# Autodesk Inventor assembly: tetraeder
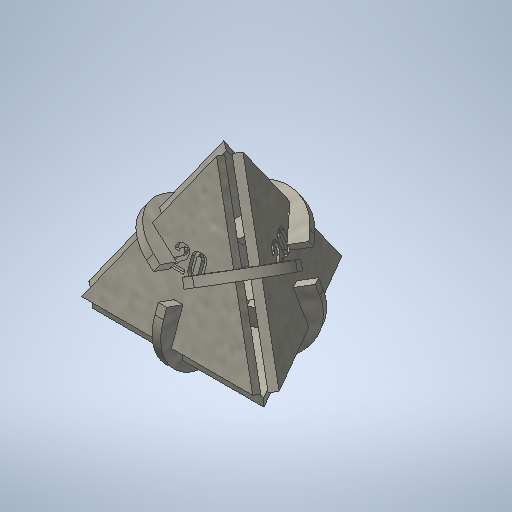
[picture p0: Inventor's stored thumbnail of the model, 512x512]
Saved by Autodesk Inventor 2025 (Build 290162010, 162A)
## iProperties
Created: 2025-02
Part Number: tetraeder
Material: Generisch
Document SubType Name: Assembly
Designer: BennF
Author: BennF
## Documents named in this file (3)
- C:\Users\BennF\OneDrive - Technische Universität Ilmenau\FabAcademy\week03\tetrahedron.iam
- C:\Users\BennF\OneDrive - Technische Universität Ilmenau\FabAcademy\week03\conector_71.ipt
- C:\Users\BennF\OneDrive - Technische Universität Ilmenau\FabAcademy\week03\triangular_tile.ipt
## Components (10 placed, 2 different names)
1. triangular_tile:1 — Mate:1, Mate:2, Mate:3, Mate:4, Mate:5, Mate:6, Mate:7, Mate:8, Mate:9
2. triangular_tile:2 — Mate:10, Mate:11, Mate:12, Mate:19, Mate:20, Mate:21
3. triangular_tile:3 — Mate:13, Mate:14, Mate:15, Mate:22, Mate:23, Mate:24
4. triangular_tile:4 — Mate:16, Mate:17, Mate:18, Mate:25, Mate:26, Mate:27
5. conector_71:1 — Mate:1, Mate:2, Mate:3, Mate:10, Mate:11, Mate:12
6. conector_71:2 — Mate:4, Mate:5, Mate:6, Mate:13, Mate:14, Mate:15
7. conector_71:3 — Mate:7, Mate:8, Mate:9, Mate:16, Mate:17, Mate:18
8. conector_71:4 — Mate:19, Mate:20, Mate:21
9. conector_71:5 — Mate:22, Mate:23, Mate:24
10. conector_71:6 — Mate:25, Mate:26, Mate:27
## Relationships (27: Mate 27)
- Mate:1: triangular_tile:1 ↔ conector_71:1
- Mate:2: triangular_tile:1 ↔ conector_71:1
- Mate:3: triangular_tile:1 ↔ conector_71:1
- Mate:4: triangular_tile:1 ↔ conector_71:2
- Mate:5: triangular_tile:1 ↔ conector_71:2
- Mate:6: triangular_tile:1 ↔ conector_71:2
- Mate:7: triangular_tile:1 ↔ conector_71:3
- Mate:8: triangular_tile:1 ↔ conector_71:3
- Mate:9: triangular_tile:1 ↔ conector_71:3
- Mate:10: triangular_tile:2 ↔ conector_71:1
- Mate:11: triangular_tile:2 ↔ conector_71:1
- Mate:12: triangular_tile:2 ↔ conector_71:1
- Mate:13: triangular_tile:3 ↔ conector_71:2
- Mate:14: triangular_tile:3 ↔ conector_71:2
- Mate:15: triangular_tile:3 ↔ conector_71:2
- Mate:16: triangular_tile:4 ↔ conector_71:3
- Mate:17: triangular_tile:4 ↔ conector_71:3
- Mate:18: triangular_tile:4 ↔ conector_71:3
- Mate:19: triangular_tile:2 ↔ conector_71:4
- Mate:20: triangular_tile:2 ↔ conector_71:4
- Mate:21: triangular_tile:2 ↔ conector_71:4
- Mate:22: triangular_tile:3 ↔ conector_71:5
- Mate:23: triangular_tile:3 ↔ conector_71:5
- Mate:24: triangular_tile:3 ↔ conector_71:5
- Mate:25: triangular_tile:4 ↔ conector_71:6
- Mate:26: triangular_tile:4 ↔ conector_71:6
- Mate:27: triangular_tile:4 ↔ conector_71:6
